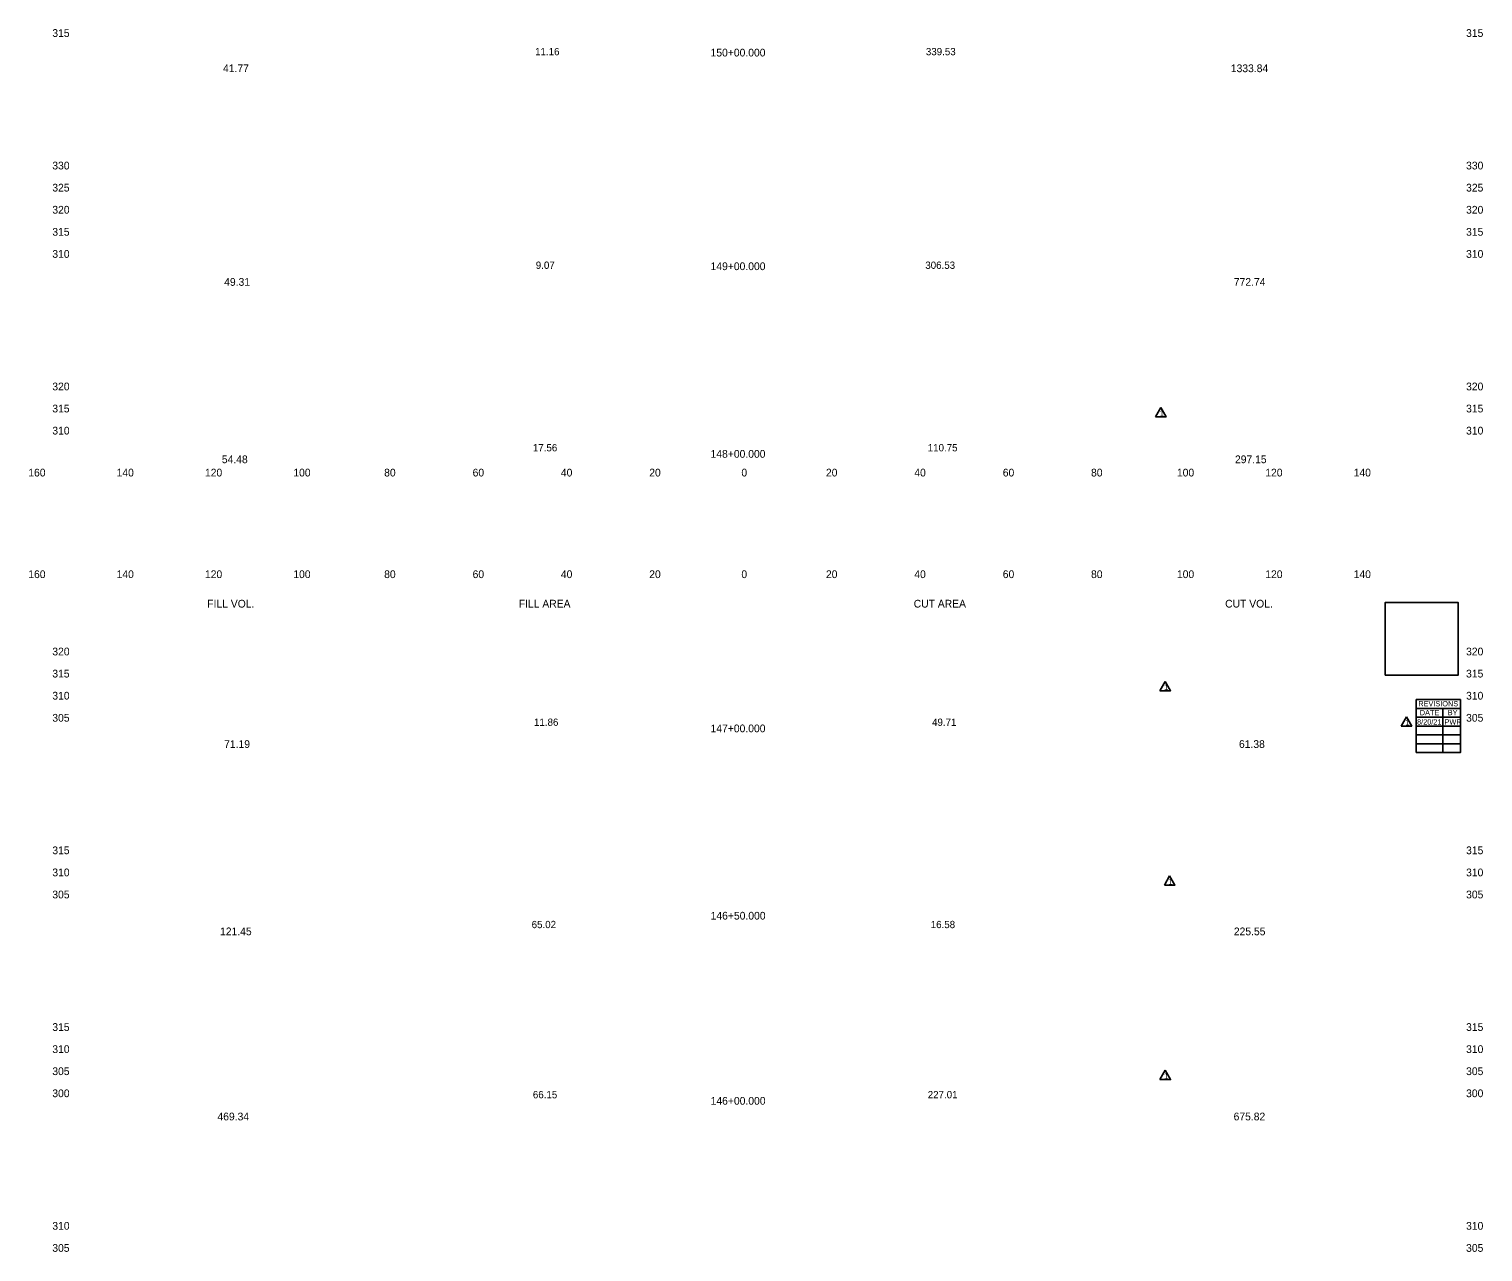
# Model space of a CAD drawing. Extents: x 21477 to 21806, y 6470 to 11049.
# Drawn here: x 21477.1 to 21806.1, y 10204.8 to 10481.6 of the extents above; entities that cross this region are included whole.
import ezdxf

# ---------------------------------------------------------------- set-up
doc = ezdxf.new("R2010")
doc.units = 0
for name, color, linetype in [('ROW_REVISION_DATA', 7, 'Continuous'), ('SHEET_CONSULTANT_STAMP', 7, 'Continuous'), ('XS_SHEET_EW_TX_AREA', 7, 'Continuous'), ('XS_SHEET_EW_TX_VOLUME', 7, 'Continuous'), ('XS_SHEET_LABELS_ELEVATION', 7, 'Continuous'), ('XS_SHEET_LABELS_OFFSET', 7, 'Continuous'), ('XS_SHEET_LABELS_STATION', 7, 'Continuous'), ('XS_SHEET_TX', 7, 'Continuous')]:
    doc.layers.add(name, color=color, linetype=linetype)

msp = doc.modelspace()

# ---------------------------------------------------------------- linework, layer by layer
at = {"layer": 'ROW_REVISION_DATA'}
for p, q in [((21732.04, 10393.84), (21733.24, 10395.92)), ((21733.04, 10331.84), (21734.24, 10333.92)), ((21801.04, 10329.84), (21801.04, 10317.84)), ((21791.04, 10327.84), (21801.04, 10327.84)), ((21797.04, 10317.84), (21797.04, 10327.84)), ((21787.64, 10323.84), (21788.84, 10325.92)), ((21791.04, 10325.84), (21801.04, 10325.84)), ((21791.04, 10323.84), (21801.04, 10323.84)), ((21791.04, 10321.84), (21801.04, 10321.84)), ((21791.04, 10319.84), (21801.04, 10319.84)), ((21797.04, 10321.84), (21797.04, 10321.84)), ((21734.04, 10287.84), (21735.24, 10289.92)), ((21733.04, 10243.84), (21734.24, 10245.92))]:
    msp.add_line(p, q, dxfattribs=at)
for points in [[(21733.24, 10395.92), (21734.44, 10393.84), (21732.04, 10393.84)], [(21734.24, 10333.92), (21735.44, 10331.84), (21733.04, 10331.84)], [(21788.84, 10325.92), (21790.04, 10323.84), (21787.64, 10323.84)], [(21735.24, 10289.92), (21736.44, 10287.84), (21734.04, 10287.84)], [(21734.24, 10245.92), (21735.44, 10243.84), (21733.04, 10243.84)]]:
    msp.add_lwpolyline(points, dxfattribs=at)
msp.add_lwpolyline([(21791.04, 10317.84), (21791.04, 10329.84), (21801.04, 10329.84), (21801.04, 10317.84)], close=True, dxfattribs=at)
at = {"layer": 'SHEET_CONSULTANT_STAMP'}
msp.add_lwpolyline([(21784.04, 10335.34), (21800.54, 10335.34), (21800.54, 10351.84), (21784.04, 10351.84)], close=True, dxfattribs=at)

# ---------------------------------------------------------------- texts
at = {"layer": 'ROW_REVISION_DATA'}
for s, height, p in [('1', 1.32, (21732.97, 10393.98)), ('1', 1.32, (21733.97, 10331.98)), ('REVISIONS', 1.2, (21791.52, 10328.31)), ('DATE', 1.2, (21791.86, 10326.29)), ('BY', 1.2, (21798.19, 10326.3)), ('1', 1.32, (21788.57, 10323.98)), ('8/20/21 ', 1.2, (21791.24, 10324.18)), ('PWR', 1.2, (21797.46, 10324.18)), ('1', 1.32, (21734.97, 10287.98)), ('1', 1.32, (21733.97, 10243.98))]:
    msp.add_text(s, height=height, dxfattribs=at).set_placement(p)
at = {"layer": 'XS_SHEET_EW_TX_AREA'}
for s, p in [(' 11.16 ', (21591, 10475.69)), (' 339.53 ', (21679.45, 10475.69)), (' 9.07 ', (21591.16, 10427.34)), (' 306.53 ', (21679.32, 10427.34)), (' 17.56 ', (21590.5, 10386.03)), (' 110.75 ', (21679.87, 10386.03)), (' 11.86 ', (21590.75, 10323.89)), (' 49.71 ', (21680.85, 10323.89)), (' 65.02 ', (21590.22, 10278.1)), (' 16.58 ', (21680.55, 10278.1)), (' 66.15 ', (21590.5, 10239.59)), (' 227.01 ', (21679.87, 10239.59))]:
    msp.add_text(s, height=1.65, dxfattribs=at).set_placement(p)
at = {"layer": 'XS_SHEET_EW_TX_VOLUME'}
for s, p in [(' 41.77 ', (21520.33, 10471.86)), (' 1333.84 ', (21748.44, 10471.86)), (' 49.31 ', (21520.59, 10423.5)), (' 772.74 ', (21749.12, 10423.5)), (' 54.48 ', (21520.06, 10383.35)), (' 297.15 ', (21749.38, 10383.35)), (' 71.19 ', (21520.58, 10318.89)), (' 61.38 ', (21750.28, 10318.89)), (' 121.45 ', (21519.65, 10276.49)), (' 225.55 ', (21749.12, 10276.49)), (' 469.34 ', (21519.07, 10234.59)), (' 675.82 ', (21749.07, 10234.59))]:
    msp.add_text(s, height=1.75, dxfattribs=at).set_placement(p)
at = {"layer": 'XS_SHEET_LABELS_ELEVATION'}
for s, p in [('  315  ', (21481.04, 10479.84)), ('  315  ', (21801.04, 10479.84)), ('  330  ', (21481.04, 10449.84)), ('  330  ', (21801.04, 10449.84)), ('  325  ', (21481.04, 10444.84)), ('  325  ', (21801.04, 10444.84)), ('  320  ', (21481.04, 10439.84)), ('  320  ', (21801.04, 10439.84)), ('  315  ', (21481.04, 10434.84)), ('  315  ', (21801.04, 10434.84)), ('  310  ', (21481.04, 10429.84)), ('  310  ', (21801.04, 10429.84)), ('  320  ', (21481.04, 10399.84)), ('  320  ', (21801.04, 10399.84)), ('  315  ', (21481.04, 10394.84)), ('  315  ', (21801.04, 10394.84)), ('  310  ', (21481.04, 10389.84)), ('  310  ', (21801.04, 10389.84)), ('  320  ', (21481.04, 10339.84)), ('  320  ', (21801.04, 10339.84)), ('  315  ', (21481.04, 10334.84)), ('  315  ', (21801.04, 10334.84)), ('  310  ', (21481.04, 10329.84)), ('  310  ', (21801.04, 10329.84)), ('  305  ', (21481.04, 10324.84)), ('  305  ', (21801.04, 10324.84)), ('  315  ', (21481.04, 10294.84)), ('  315  ', (21801.04, 10294.84)), ('  310  ', (21481.04, 10289.84)), ('  310  ', (21801.04, 10289.84)), ('  305  ', (21481.04, 10284.84)), ('  305  ', (21801.04, 10284.84)), ('  315  ', (21481.04, 10254.84)), ('  315  ', (21801.04, 10254.84)), ('  310  ', (21481.04, 10249.84)), ('  310  ', (21801.04, 10249.84)), ('  305  ', (21481.04, 10244.84)), ('  305  ', (21801.04, 10244.84)), ('  300  ', (21481.04, 10239.84)), ('  300  ', (21801.04, 10239.84)), ('  310  ', (21481.04, 10209.84)), ('  310  ', (21801.04, 10209.84)), ('  305  ', (21481.04, 10204.84)), ('  305  ', (21801.04, 10204.84))]:
    msp.add_text(s, height=1.75, dxfattribs=at).set_placement(p)
at = {"layer": 'XS_SHEET_LABELS_OFFSET'}
for s, p in [('  160  ', (21475.6, 10380.34)), ('  140  ', (21495.59, 10380.34)), ('  120  ', (21515.59, 10380.34)), ('  100  ', (21535.59, 10380.34)), ('  80  ', (21556.15, 10380.34)), ('  60  ', (21576.17, 10380.34)), ('  40  ', (21596.15, 10380.34)), ('  20  ', (21616.15, 10380.34)), ('  0  ', (21637.01, 10380.34)), ('  0  ', (21637.01, 10380.34)), ('  20  ', (21656.15, 10380.34)), ('  40  ', (21676.15, 10380.34)), ('  60  ', (21696.17, 10380.34)), ('  80  ', (21716.15, 10380.34)), ('  100  ', (21735.59, 10380.34)), ('  120  ', (21755.59, 10380.34)), ('  140  ', (21775.59, 10380.34)), ('  160  ', (21475.6, 10357.34)), ('  140  ', (21495.59, 10357.34)), ('  120  ', (21515.59, 10357.34)), ('  100  ', (21535.59, 10357.34)), ('  80  ', (21556.15, 10357.34)), ('  60  ', (21576.17, 10357.34)), ('  40  ', (21596.15, 10357.34)), ('  20  ', (21616.15, 10357.34)), ('  0  ', (21637.01, 10357.34)), ('  0  ', (21637.01, 10357.34)), ('  20  ', (21656.15, 10357.34)), ('  40  ', (21676.15, 10357.34)), ('  60  ', (21696.17, 10357.34)), ('  80  ', (21716.15, 10357.34)), ('  100  ', (21735.59, 10357.34)), ('  120  ', (21755.59, 10357.34)), ('  140  ', (21775.59, 10357.34))]:
    msp.add_text(s, height=1.75, dxfattribs=at).set_placement(p)
at = {"layer": 'XS_SHEET_LABELS_STATION'}
for s, p in [('  150+00.000  ', (21630.03, 10475.41)), ('  149+00.000  ', (21630.03, 10427.05)), ('  148+00.000  ', (21630.03, 10384.58)), ('  147+00.000  ', (21630.03, 10322.44)), ('  146+50.000  ', (21630.05, 10280.04)), ('  146+00.000  ', (21630.05, 10238.14))]:
    msp.add_text(s, height=1.75, dxfattribs=at).set_placement(p)
at = {"layer": 'XS_SHEET_TX'}
for s, p in [('FILL VOL.', (21517.41, 10350.67)), ('FILL AREA', (21587.92, 10350.67)), ('CUT AREA', (21677.31, 10350.67)), ('CUT VOL.', (21747.8, 10350.67))]:
    msp.add_text(s, height=1.75, dxfattribs=at).set_placement(p)

doc.saveas('drawing.dxf')
